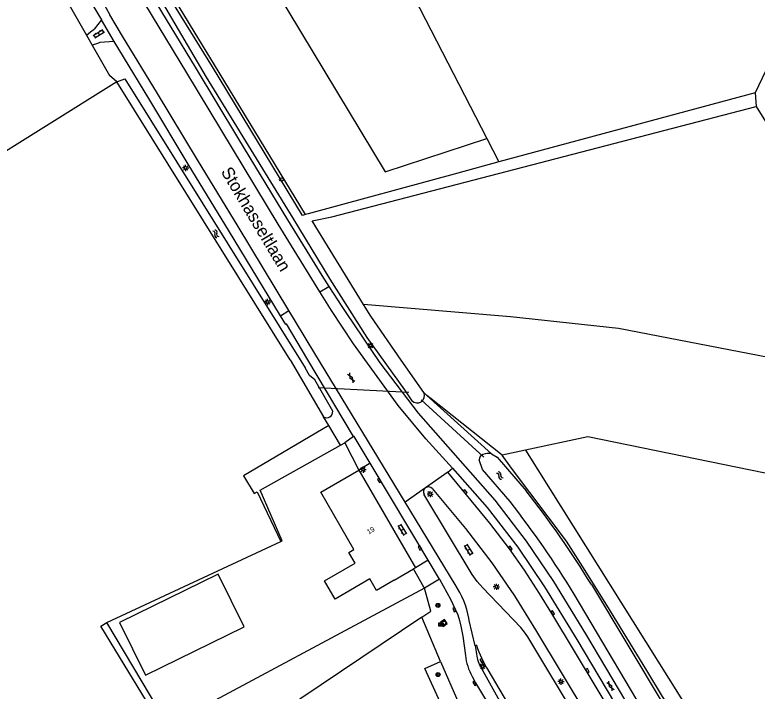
# Model space of a CAD drawing. Extents: x 133000 to 136000, y 400500 to 403500.
# Drawn here: x 133444.8 to 133593.4, y 401055.6 to 401191 of the extents above; entities that cross this region are included whole.
import ezdxf

# ---------------------------------------------------------------- set-up
doc = ezdxf.new("R2010")
doc.units = 0
for name, color, linetype in [('gg-afsc-draadraster', 7, 'Continuous'), ('gg-afsc-erfafscheiding', 7, 'Continuous'), ('gg-afsc-hekwerk', 7, 'Continuous'), ('gg-anno-huisnummerreeks BGT', 7, 'Continuous'), ('gg-anno-openbare ruimte label', 7, 'Continuous'), ('gg-bbg-gedigitaliseerde bijgebouw', 7, 'Continuous'), ('gg-bbg-hoofdgebouw', 7, 'Continuous'), ('gg-knt-bronhoudergrens', 7, 'Continuous'), ('gg-knt-verharding', 7, 'Continuous'), ('gg-kntw-bovenkant insteek waterloop', 7, 'Continuous'), ('gg-kntw-greppel-droge sloot', 7, 'Continuous'), ('gg-kwrk-duiker nz buis', 7, 'Continuous'), ('gt-grn-groengrens', 7, 'Continuous'), ('gt-grn-weggrens', 7, 'Continuous'), ('gt-symb-boom', 7, 'Continuous'), ('gt-symb-brandkraan', 7, 'Continuous'), ('gt-symb-gesloten verharding', 7, 'Continuous'), ('gt-symb-klinker verharding', 7, 'Continuous'), ('gt-symb-kolk', 7, 'Continuous'), ('gt-symb-lichtmast', 7, 'Continuous'), ('gt-symb-rioolkast', 7, 'Continuous'), ('gt-symb-rioolschacht', 7, 'Continuous'), ('gt-symb-watersymbool', 7, 'Continuous')]:
    doc.layers.add(name, color=color, linetype=linetype)

# ---------------------------------------------------------------- blocks, each defined once
blk = doc.blocks.new('gt0-GESVH1')
at = {"layer": 'gt-symb-gesloten verharding'}
for p, q in [((-0.99, -0.26), (0.01, 0.24)), ((0.01, -0.26), (-0.99, 0.24)), ((0.01, 0.24), (1.01, -0.26)), ((1.01, 0.24), (0.01, -0.26))]:
    blk.add_line(p, q, dxfattribs=at)
blk = doc.blocks.new('gt0-KOLK')
at = {"layer": 'gt-symb-kolk'}
blk.add_lwpolyline([(0, 0), (0.38, 0), (0.38, 0.4), (-0.37, 0.4), (-0.37, 0), (0, 0)], dxfattribs=at)
blk = doc.blocks.new('gt0-LMAST')
at = {"layer": 'gt-symb-lichtmast'}
for p, q in [((-0.18, 0.17), (-0.45, 0.44)), ((-0.01, 0.25), (-0.01, 0.62)), ((0.17, 0.17), (0.44, 0.44)), ((-0.26, 0), (-0.63, 0)), ((-0.18, -0.18), (-0.45, -0.45)), ((-0.01, -0.25), (-0.01, -0.63)), ((0.44, -0.45), (0.17, -0.18)), ((0.24, 0), (0.62, 0))]:
    blk.add_line(p, q, dxfattribs=at)
blk.add_circle((-0.01, 0), 0.25, dxfattribs=at)
blk = doc.blocks.new('gt0-BOOM')
at = {"layer": 'gt-symb-boom'}
for radius in [0.4, 0.2]:
    blk.add_circle((0, 0), radius, dxfattribs=at)
blk = doc.blocks.new('gt0-RKAST')
at = {"layer": 'gt-symb-rioolkast'}
for p, q in [((-0.5, -0.25), (0.5, 0.25)), ((-0.5, 0.25), (0.5, -0.25))]:
    blk.add_line(p, q, dxfattribs=at)
blk.add_lwpolyline([(0.5, 0.25), (-0.5, 0.25), (-0.5, -0.25), (0.5, -0.25)], close=True, dxfattribs=at)
blk = doc.blocks.new('gt0-RS')
at = {"layer": 'gt-symb-rioolschacht'}
blk.add_lwpolyline([(-0.5, -0.5), (0.5, -0.5), (0.5, 0.5), (-0.5, 0.5)], close=True, dxfattribs=at)
blk.add_circle((0, 0), 0.375, dxfattribs=at)
blk = doc.blocks.new('gt0-KL1')
at = {"layer": 'gt-symb-klinker verharding'}
for p, q in [((-1.15, 0.3), (1.15, 0.3)), ((-1, -0.3), (-1, 0.3)), ((-0.5, 0.3), (-0.5, 0.45)), ((0, -0.3), (0, 0.3)), ((0.5, 0.3), (0.5, 0.45)), ((1, -0.3), (1, 0.3)), ((-1.15, -0.3), (1.15, -0.3)), ((-0.5, -0.45), (-0.5, -0.3)), ((0.5, -0.45), (0.5, -0.3))]:
    blk.add_line(p, q, dxfattribs=at)
blk = doc.blocks.new('gt0-WA')
at = {"layer": 'gt-symb-watersymbool'}
for centre, start, end in [((-0.32, 0.02), 28.0725, 151.9275), ((0.43, 0.42), 208.0725, 331.9275), ((-0.32, -0.43), 28.0725, 151.9275), ((0.43, -0.03), 208.0725, 331.9275)]:
    blk.add_arc(centre, 0.425, start, end, dxfattribs=at)
blk = doc.blocks.new('gt0-BR')
at = {"layer": 'gt-symb-brandkraan'}
for centre, radius, start, end in [((-0.24, 0), 0.206, 107.5669, 252.4331), ((0.6, -2.66), 3, 106.892, 107.5669), ((0, -0.69), 0.938, 73.108, 106.892), ((-0.6, -2.66), 3, 72.4331, 73.108), ((0.24, 0), 0.206, 287.567, 72.4331), ((0.6, 2.66), 3, 252.4331, 253.108), ((0, 0.69), 0.938, 253.108, 286.8921), ((-0.6, 2.66), 3, 286.8921, 287.567)]:
    blk.add_arc(centre, radius, start, end, dxfattribs=at)

msp = doc.modelspace()

# ---------------------------------------------------------------- linework, layer by layer
at = {"layer": 'gg-afsc-draadraster'}
for p, q in [((133518.58, 401206.4), (133539.23, 401166.31)), ((133539.23, 401166.31), (133541.66, 401161.58)), ((133529.97, 401061.6), (133526.27, 401070.47))]:
    msp.add_line(p, q, dxfattribs=at)
for points in [[(133465.2, 401177.6), (133436.96, 401160.03), (133396.55, 401135.16), (133384.57, 401127.31)], [(133526.27, 401070.47), (133528.05, 401071.66), (133526.77, 401076.24)], [(133548.98, 401011.54), (133526.85, 401060.17), (133529.97, 401061.6)], [(133529.97, 401061.6), (133537.32, 401044.74), (133544.3, 401029.21), (133551.74, 401012.71)]]:
    msp.add_lwpolyline(points, dxfattribs=at)
at = {"layer": 'gg-afsc-erfafscheiding'}
msp.add_line((133480.67, 401187.72), (133475.18, 401196.72), dxfattribs=at)
msp.add_lwpolyline([(133502.98, 401151.05), (133484.76, 401181.03), (133480.67, 401187.72)], dxfattribs=at)
at = {"layer": 'gg-afsc-hekwerk'}
for p, q in [((133459.11, 401186.98), (133460.27, 401184.96)), ((133460.27, 401184.96), (133463.75, 401178.89)), ((133528.11, 401114.13), (133527.23, 401114.83)), ((133542.35, 401102.86), (133528.11, 401114.13)), ((133509.99, 401104.89), (133510.85, 401105.36)), ((133463.2, 401069.36), (133498, 401085.59))]:
    msp.add_line(p, q, dxfattribs=at)
for points in [[(133435.08, 401220.54), (133439.67, 401220.88), (133459.11, 401186.98)], [(133498, 401085.59), (133498.26, 401085.71), (133493.87, 401095.9), (133509.99, 401104.89)], [(133654.12, 401074.5), (133649.97, 401072.09), (133618.45, 401053.28), (133591.98, 401037.34), (133586.65, 401040.93), (133582.05, 401045.23), (133577.57, 401049.8), (133574.45, 401054.54), (133571.28, 401059.77), (133563.26, 401072.86), (133558.49, 401080.51), (133555.19, 401085.65), (133544.2, 401100.25), (133542.35, 401102.86)], [(133526.77, 401076.24), (133475.46, 401048.77), (133463.2, 401069.36)]]:
    msp.add_lwpolyline(points, dxfattribs=at)
at = {"layer": 'gg-bbg-gedigitaliseerde bijgebouw'}
msp.add_lwpolyline([(133465.72, 401069.38), (133470.9, 401058.84), (133490.65, 401068.54), (133485.45, 401079.07), (133465.72, 401069.38)], dxfattribs=at)
at = {"layer": 'gg-bbg-hoofdgebouw'}
for p, q in [((133513.62, 401099.88), (133525, 401080.35)), ((133525, 401080.35), (133524.56, 401080.09)), ((133520.68, 401077.83), (133524.56, 401080.09))]:
    msp.add_line(p, q, dxfattribs=at)
msp.add_lwpolyline([(133520.68, 401077.83), (133517.2, 401075.8), (133515.87, 401078.09), (133508.89, 401074.03), (133506.74, 401077.71), (133512.87, 401081.29), (133511.62, 401083.42), (133512.66, 401084.02), (133506.01, 401095.44), (133513.62, 401099.88)], dxfattribs=at)
at = {"layer": 'gg-knt-bronhoudergrens'}
for points in [[(133507.6, 401108.83), (133490.58, 401098.77), (133492.69, 401095.21), (133493.28, 401095.55), (133498, 401085.59)], [(133526.27, 401070.47), (133497.95, 401051.41), (133505.15, 401039.1), (133497.95, 401034.68), (133486.84, 401027.87), (133461.98, 401068.62), (133463.2, 401069.36)]]:
    msp.add_lwpolyline(points, dxfattribs=at)
at = {"layer": 'gg-knt-verharding'}
for p, q in [((133462.1, 401190.02), (133460.62, 401188.19)), ((133464.64, 401185.73), (133462.1, 401190.02)), ((133464.64, 401185.73), (133461.77, 401185.49)), ((133512.59, 401106.63), (133510.85, 401105.36)), ((133510.85, 401105.36), (133513.62, 401099.88)), ((133527.51, 401081.85), (133515.93, 401101.25)), ((133531.44, 401099.47), (133532.39, 401100.25)), ((133526.98, 401096.35), (133526.99, 401096.36)), ((133532.9, 401076.97), (133522.88, 401093.48)), ((133529.76, 401078.07), (133527.51, 401081.85)), ((133526.67, 401076.43), (133524.56, 401080.09)), ((133529.76, 401078.07), (133526.77, 401076.24)), ((133526.77, 401076.24), (133526.67, 401076.43)), ((133537.17, 401064.82), (133536.95, 401064.72)), ((133555.97, 401032.46), (133539.51, 401059.87))]:
    msp.add_line(p, q, dxfattribs=at)
for points in [[(133471.15, 401196.63), (133480.87, 401180.59), (133489.56, 401166.18), (133499.36, 401149.97), (133506.23, 401138.84), (133507.63, 401136.68)], [(133505.84, 401135.59), (133497.52, 401149.11), (133479.23, 401179.41), (133469.44, 401195.6)], [(133499.64, 401131.83), (133489.46, 401148.67), (133481.35, 401162.01), (133473.32, 401175.32), (133466.35, 401186.77), (133463.82, 401191.04)], [(133459.11, 401186.98), (133459.9, 401187.61), (133460.62, 401188.19)], [(133497.93, 401130.8), (133487.54, 401147.93), (133479.7, 401160.81), (133471.61, 401174.28), (133464.64, 401185.73)], [(133461.77, 401185.49), (133461.3, 401185.32), (133460.27, 401184.96)], [(133507.63, 401136.68), (133510.24, 401132.67), (133511.05, 401131.47)], [(133532.39, 401100.25), (133527.08, 401106.12), (133521.52, 401112.85), (133512.57, 401125.16), (133508.15, 401131.84), (133505.84, 401135.59)], [(133512.59, 401106.63), (133503.41, 401121.97), (133499.15, 401129.15), (133498.99, 401129.05), (133497.93, 401130.8)], [(133522.88, 401093.48), (133504.85, 401123.21), (133500.96, 401129.65), (133499.64, 401131.83)], [(133511.05, 401131.47), (133517.82, 401121.34), (133525.52, 401111.31), (133540.84, 401093.84), (133547.12, 401085.68), (133552.59, 401077.56), (133559.03, 401067.09), (133571.02, 401046.91)], [(133515.93, 401101.25), (133512.72, 401106.63), (133512.59, 401106.63)], [(133532.39, 401100.25), (133539.33, 401092.38), (133545.48, 401084.43), (133550.79, 401076.49), (133557.25, 401065.96), (133569.21, 401045.87)], [(133570.25, 401041.38), (133552.27, 401071.2), (133549.82, 401075.17), (133546.79, 401079.84), (133543.81, 401084.1), (133539.85, 401089.26), (133531.44, 401099.47)], [(133567.74, 401032.74), (133547.46, 401066.52), (133546.83, 401067.47), (133546.09, 401068.39), (133538.43, 401076.32), (133537.32, 401077.61), (133536.35, 401079.01), (133526.68, 401095.05)], [(133528.3, 401096.2), (133534.98, 401088.2), (133540.26, 401081.34), (133544.79, 401074.72), (133549.02, 401067.9), (133569.97, 401033.05)], [(133529.76, 401078.07), (133531.99, 401074.06), (133533.43, 401070.91), (133533.82, 401069.78), (133534.08, 401068.62), (133534.44, 401066.65), (133534.96, 401062.76)], [(133536.95, 401064.72), (133535.75, 401069.81), (133535.67, 401070.22)], [(133536.95, 401064.72), (133536.99, 401064.4), (133537.16, 401063.02)], [(133538.14, 401060.27), (133542.77, 401051.88), (133554.46, 401032.33)], [(133536.32, 401058.59), (133536.99, 401057.3), (133540.72, 401051.12), (133551.77, 401032.6)]]:
    msp.add_lwpolyline(points, dxfattribs=at)
for centre, radius, start, end in [((135147.9, 402169.75), 1947.82, 208.68031, 210.16323), ((134720.52, 401936.31), 1463.07, 209.18599, 210.66988), ((133527.56, 401095.53), 1, 41.6468, 124.5542), ((133527.56, 401095.53), 1, 125.3449, 209.1226), ((133518.24, 401067.01), 17.72, 10.4153, 34.1904), ((133560.11, 401072.64), 24.24, 198.8147, 211.8001), ((133546.04, 401064.05), 11.15, 186.6252, 209.3366), ((133544.71, 401064.16), 7.63, 188.5921, 210.6707)]:
    msp.add_arc(centre, radius, start, end, dxfattribs=at)
at = {"layer": 'gg-kntw-bovenkant insteek waterloop'}
for p, q in [((133499.91, 401121.96), (133465.2, 401177.6)), ((133593.16, 401172.71), (133599.66, 401162.19)), ((133499.91, 401121.96), (133506.57, 401110.54)), ((133540.2, 401103.12), (133541.31, 401102.48)), ((133541.31, 401102.48), (133547.12, 401095.72)), ((133560.2, 401076.98), (133574.57, 401053.03)), ((133571.13, 401050.8), (133556.75, 401075.06))]:
    msp.add_line(p, q, dxfattribs=at)
for points in [[(133629.21, 401268.74), (133630.22, 401264.05), (133630.7, 401261.44), (133630.54, 401257.89), (133621.9, 401238.8), (133608.53, 401209.65), (133596.44, 401182.68), (133592.99, 401175.42)], [(133465.2, 401177.6), (133466.79, 401178.24), (133502.87, 401120.39)], [(133508.41, 401111.67), (133504.8, 401117.93), (133503.79, 401118.8), (133502.87, 401120.39)], [(133543.94, 401093.59), (133538.41, 401100.04), (133537.74, 401101.94)]]:
    msp.add_lwpolyline(points, dxfattribs=at)
for centre, radius, start, end in [((133507.2, 401111.58), 1.22, 239.0134, 4.0418), ((133539, 401101.88), 1.26, 114.4528, 177.4436), ((133539.47, 401100.48), 2.74, 74.6619, 111.2095), ((133397.43, 400977.35), 190.83, 31.4687, 38.3363), ((133379.87, 400966.48), 207.55, 31.545, 37.7678)]:
    msp.add_arc(centre, radius, start, end, dxfattribs=at)
at = {"layer": 'gg-kntw-greppel-droge sloot'}
for p, q in [((133592.99, 401175.42), (133541.66, 401161.58)), ((133592.99, 401175.42), (133593.16, 401172.71)), ((133508.22, 401150.61), (133593.16, 401172.71)), ((133502.98, 401151.05), (133502.38, 401150.89)), ((133503.5, 401151.2), (133502.98, 401151.05)), ((133522.78, 401115.98), (133524.26, 401113.79))]:
    msp.add_line(p, q, dxfattribs=at)
for points in [[(133502.38, 401150.89), (133484.32, 401180.65), (133471.89, 401200.83), (133464.97, 401212.45), (133460.75, 401219.62), (133458.57, 401224.06), (133458.49, 401225.58), (133457.22, 401225.71), (133456.89, 401225.09), (133457.02, 401223.16), (133459.95, 401217.81), (133466.19, 401207.08), (133474.3, 401193.45), (133483.06, 401178.56), (133500.45, 401150.36)], [(133541.66, 401161.58), (133533.45, 401159.37), (133503.5, 401151.2)], [(133500.45, 401150.36), (133507.84, 401138.15), (133515.27, 401126.44), (133522.78, 401115.98)], [(133514.59, 401133.03), (133504.32, 401149.78), (133508.22, 401150.61)], [(133526.67, 401115.41), (133522.08, 401121.88), (133516.02, 401130.68), (133514.59, 401133.03)]]:
    msp.add_lwpolyline(points, dxfattribs=at)
msp.add_arc((133525.32, 401114.81), 1.47, 223.7446, 23.9314, dxfattribs=at)
at = {"layer": 'gg-kwrk-duiker nz buis'}
for p, q in [((133523.64, 401115.42), (133505.49, 401116.39)), ((133526.13, 401113.96), (133538.67, 401102.45))]:
    msp.add_line(p, q, dxfattribs=at)
at = {"layer": 'gt-grn-groengrens'}
for p, q in [((133465.2, 401177.6), (133463.75, 401178.89)), ((133527.23, 401114.83), (133526.67, 401115.41)), ((133540.2, 401103.12), (133527.23, 401114.83)), ((133507.6, 401108.83), (133506.57, 401110.54)), ((133509.99, 401104.89), (133507.6, 401108.83)), ((133547.02, 401103.88), (133542.35, 401102.86))]:
    msp.add_line(p, q, dxfattribs=at)
for points in [[(133497.06, 401195.83), (133518.89, 401159.58), (133539.23, 401166.31)], [(133628.11, 401116.15), (133565.64, 401128.22), (133544, 401130.57), (133514.59, 401133.03)], [(133646.06, 401086.95), (133600.19, 401098.21), (133559.49, 401106.58), (133547.02, 401103.88)], [(133547.02, 401103.88), (133580.55, 401050.39), (133587.72, 401044.13), (133591.74, 401041.32), (133652.29, 401077.19)]]:
    msp.add_lwpolyline(points, dxfattribs=at)
at = {"layer": 'gt-grn-weggrens'}
for p, q in [((133505.84, 401135.59), (133507.63, 401136.68)), ((133497.93, 401130.8), (133499.64, 401131.83)), ((133515.93, 401101.25), (133513.62, 401099.88)), ((133531.44, 401099.47), (133526.99, 401096.36)), ((133526.98, 401096.35), (133522.88, 401093.48)), ((133527.51, 401081.85), (133525, 401080.35))]:
    msp.add_line(p, q, dxfattribs=at)

# ---------------------------------------------------------------- block references
at = {"layer": 'gt-symb-boom'}
for p in [(133529.48, 401072.8), (133529.5, 401058.95)]:
    msp.add_blockref('gt0-BOOM', p, dxfattribs=at)
at = {"layer": 'gt-symb-brandkraan'}
msp.add_blockref('gt0-BR', (133498.14, 401158.07), dxfattribs=at)
at = {"layer": 'gt-symb-gesloten verharding'}
for p, rotation in [((133512.12, 401118.37), -58.86920085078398), ((133564.02, 401056.67), -58.99693247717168)]:
    msp.add_blockref('gt0-GESVH1', p, dxfattribs=dict(at, rotation=rotation))
at = {"layer": 'gt-symb-klinker verharding'}
for p, rotation in [((133461.59, 401187.27), 31.72006011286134), ((133522.31, 401087.94), -59.79306598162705), ((133535.58, 401083.93), -58.99693247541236)]:
    msp.add_blockref('gt0-KL1', p, dxfattribs=dict(at, rotation=rotation))
at = {"layer": 'gt-symb-kolk'}
for p, rotation in [((133517.92, 401097.91), 120.92445902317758), ((133534.79, 401095.43), -50.275137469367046), ((133526.03, 401084.38), 120.5410984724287), ((133543.81, 401084.1), -52.43140797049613), ((133532.94, 401072.04), 113.5145566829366), ((133552.27, 401071.2), -58.27993988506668), ((133538.42, 401061.83), 116.48817853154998), ((133559.23, 401059.65), -58.94783928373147), ((133536.99, 401057.3), 121.08172983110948)]:
    msp.add_blockref('gt0-KOLK', p, dxfattribs=dict(at, rotation=rotation))
at = {"layer": 'gt-symb-lichtmast'}
for p in [(133478.96, 401160.4), (133495.37, 401133.56), (133515.98, 401124.8), (133514.49, 401099.99), (133527.93, 401095.07), (133541.19, 401076.52), (133538.44, 401060.63), (133554.1, 401057.54)]:
    msp.add_blockref('gt0-LMAST', p, dxfattribs=at)
at = {"layer": 'gt-symb-rioolkast'}
msp.add_blockref('gt0-RKAST', (133530.07, 401068.97), dxfattribs=at)
at = {"layer": 'gt-symb-rioolschacht', "rotation": -57.37496440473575}
msp.add_blockref('gt0-RS', (133530.66, 401069.3), dxfattribs=at)
at = {"layer": 'gt-symb-watersymbool'}
for p, rotation in [((133485, 401147.25), -58.04322917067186), ((133541.83, 401098.84), -49.3800604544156)]:
    msp.add_blockref('gt0-WA', p, dxfattribs=dict(at, rotation=rotation))

# ---------------------------------------------------------------- texts
at = {"layer": 'gg-anno-huisnummerreeks BGT'}
msp.add_text('19', height=1, rotation=30.2, dxfattribs=at).set_placement((133515.6, 401086.99))
at = {"layer": 'gg-anno-openbare ruimte label'}
msp.add_text('Stokhasseltlaan', height=2.5, rotation=300.8, dxfattribs=at).set_placement((133485.94, 401159.65))

doc.saveas('drawing.dxf')
